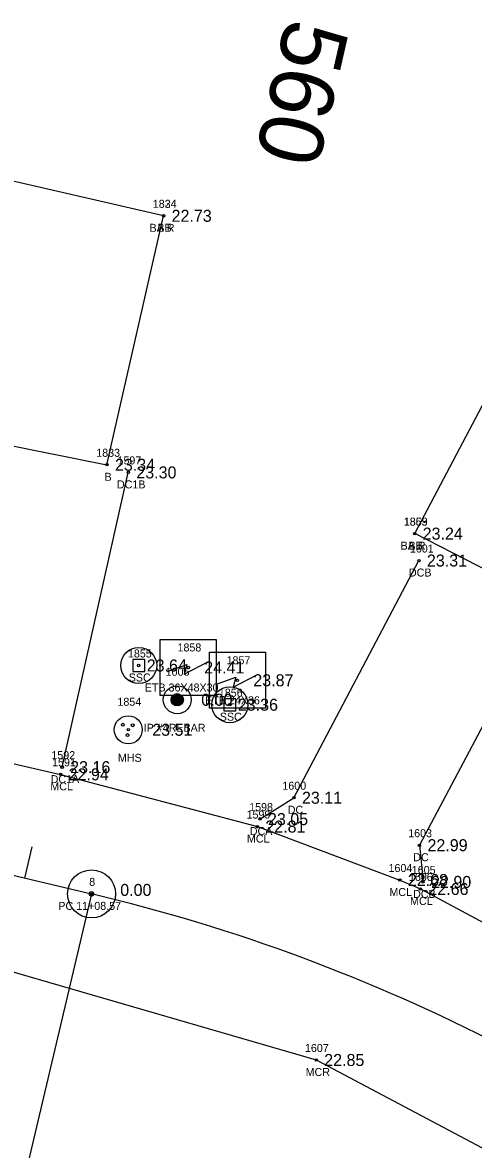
# Model space of a CAD drawing. Extents: x 2654414 to 2656963, y 761776 to 764965.
# Drawn here: x 2655707.7 to 2655764.1, y 762727.3 to 762868.1 of the extents above; entities that cross this region are included whole.
import ezdxf

# ---------------------------------------------------------------- set-up
doc = ezdxf.new("R2010")
doc.units = 0
for name, color, linetype in [('RD_EX_Bldg', 7, 'Continuous'), ('RD_EX_Bldg_txCode', 7, 'Continuous'), ('RD_EX_Conc', 7, 'Continuous'), ('RD_EX_Conc_txCode', 7, 'Continuous'), ('RD_EX_DR_Inlet', 7, 'Continuous'), ('RD_EX_DV_Prop_txCode', 7, 'Continuous'), ('RD_EX_DV_PropPin', 7, 'Continuous'), ('RD_EX_TX_Bldg_ELEV', 7, 'Continuous'), ('RD_EX_TX_Conc_ELEV', 7, 'Continuous'), ('RD_EX_TX_DV_Prop_ELEV', 7, 'Continuous'), ('RD_EX_TX_UT_ELEV', 7, 'Continuous'), ('RD_EX_UT', 7, 'Continuous'), ('RD_EX_UT_txCode', 7, 'Continuous'), ('RD_HC_Cl', 7, 'Continuous'), ('RD_HC_Data', 7, 'Continuous'), ('RD_HC_Data_Tic', 7, 'Continuous'), ('RD_HC_Survey_ELEV', 7, 'Continuous'), ('RD_HC_TX_Sta50', 7, 'Continuous'), ('RD_HC_txCode', 7, 'Continuous'), ('RD_SMD_Locator', 7, 'Continuous')]:
    doc.layers.add(name, color=color, linetype=linetype)

msp = doc.modelspace()

# ---------------------------------------------------------------- linework, layer by layer
at = {"layer": 'RD_EX_Bldg'}
for points in [[(2655725.31, 762843.91), (2655691.97, 762851.59), (2655684.61, 762819.54), (2655718.23, 762812.81), (2655725.31, 762843.91)], [(2655756.7, 762804.21), (2655774.78, 762838.43), (2655800.99, 762824.42), (2655783.66, 762790.4), (2655756.7, 762804.21)]]:
    msp.add_lwpolyline(points, dxfattribs=at)
at = {"layer": 'RD_EX_Conc'}
msp.add_line((2655712.63, 762775.04), (2655720.9, 762811.86), dxfattribs=at)
for points in [[(2655737.36, 762768.55), (2655741.61, 762771.22), (2655757.23, 762800.85)], [(2655647.95, 762795.55), (2655656.5, 762788.85), (2655668.3, 762784.32), (2655695.43, 762778.05), (2655712.44, 762774.14), (2655737.03, 762767.62), (2655754.84, 762760.94), (2655757.41, 762759.82), (2655785.93, 762744.56)], [(2655771.89, 762792.77), (2655757.3, 762765.29), (2655757.75, 762760.7)], [(2655638.83, 762758.42), (2655640.65, 762759.07), (2655648.88, 762760.53), (2655656.27, 762760.57), (2655663.1, 762759.53), (2655700.27, 762751.26), (2655744.39, 762738.46), (2655772.67, 762723.5), (2655774.32, 762722.61)]]:
    msp.add_lwpolyline(points, dxfattribs=at)
at = {"layer": 'RD_EX_DR_Inlet'}
for centre, radius in [((2655720.89, 762779.71), 1.75), ((2655720.22, 762780.34), 0.175), ((2655720.8, 762779.05), 0.175), ((2655721.45, 762780.27), 0.175)]:
    msp.add_circle(centre, radius, dxfattribs=at)
at = {"layer": 'RD_EX_DV_PropPin'}
for p, q in [((2655726.28, 762783.26), (2655726.28, 762783.65)), ((2655726.32, 762783.16), (2655726.32, 762783.75)), ((2655726.35, 762783.09), (2655726.35, 762783.82)), ((2655726.39, 762783.03), (2655726.39, 762783.88)), ((2655726.42, 762782.98), (2655726.42, 762783.93)), ((2655726.46, 762782.94), (2655726.46, 762783.97)), ((2655726.49, 762782.9), (2655726.49, 762784.01)), ((2655726.53, 762782.87), (2655726.53, 762784.04)), ((2655726.56, 762782.85), (2655726.56, 762784.06)), ((2655726.6, 762782.82), (2655726.6, 762784.09)), ((2655726.63, 762782.8), (2655726.63, 762784.11)), ((2655726.67, 762782.78), (2655726.67, 762784.13)), ((2655726.7, 762782.76), (2655726.7, 762784.15)), ((2655726.74, 762782.75), (2655726.74, 762784.16)), ((2655726.77, 762782.73), (2655726.77, 762784.18)), ((2655726.81, 762782.72), (2655726.81, 762784.19)), ((2655726.84, 762782.71), (2655726.84, 762784.2)), ((2655726.88, 762782.71), (2655726.88, 762784.2)), ((2655726.91, 762782.7), (2655726.91, 762784.21)), ((2655726.95, 762782.7), (2655726.95, 762784.21)), ((2655726.98, 762782.69), (2655726.98, 762784.22)), ((2655727.02, 762782.69), (2655727.02, 762784.22)), ((2655727.05, 762782.69), (2655727.05, 762784.22)), ((2655727.09, 762782.7), (2655727.09, 762784.21)), ((2655727.12, 762782.7), (2655727.12, 762784.21)), ((2655727.16, 762782.71), (2655727.16, 762784.2)), ((2655727.19, 762782.71), (2655727.19, 762784.2)), ((2655727.23, 762782.72), (2655727.23, 762784.19)), ((2655727.26, 762782.73), (2655727.26, 762784.18)), ((2655727.3, 762782.75), (2655727.3, 762784.16)), ((2655727.33, 762782.76), (2655727.33, 762784.15)), ((2655727.37, 762782.78), (2655727.37, 762784.13)), ((2655727.4, 762782.8), (2655727.4, 762784.11)), ((2655727.44, 762782.82), (2655727.44, 762784.09)), ((2655727.47, 762782.85), (2655727.47, 762784.06)), ((2655727.51, 762782.87), (2655727.51, 762784.04)), ((2655727.54, 762782.9), (2655727.54, 762784.01)), ((2655727.58, 762782.94), (2655727.58, 762783.97)), ((2655727.61, 762782.98), (2655727.61, 762783.93)), ((2655727.65, 762783.03), (2655727.65, 762783.88)), ((2655727.68, 762783.09), (2655727.68, 762783.82)), ((2655727.72, 762783.16), (2655727.72, 762783.75)), ((2655727.75, 762783.26), (2655727.75, 762783.65))]:
    msp.add_line(p, q, dxfattribs=at)
for radius in [1.75, 0.761]:
    msp.add_circle((2655727.02, 762783.46), radius, dxfattribs=at)
at = {"layer": 'RD_EX_UT'}
for p, q in [((2655722.95, 762788.49), (2655721.45, 762788.49)), ((2655721.45, 762788.49), (2655721.45, 762786.99)), ((2655722.95, 762786.99), (2655722.95, 762788.49)), ((2655721.45, 762786.99), (2655722.95, 762786.99)), ((2655734.34, 762783.59), (2655732.84, 762783.59)), ((2655732.84, 762783.59), (2655732.84, 762782.09)), ((2655734.34, 762782.09), (2655734.34, 762783.59)), ((2655732.84, 762782.09), (2655734.34, 762782.09))]:
    msp.add_line(p, q, dxfattribs=at)
for points in [[(2655724.89, 762783.99), (2655724.89, 762790.99), (2655731.89, 762790.99), (2655731.89, 762783.99)], [(2655731.03, 762782.39), (2655731.03, 762789.39), (2655738.03, 762789.39), (2655738.03, 762782.39)]]:
    msp.add_lwpolyline(points, close=True, dxfattribs=at)
for points in [[(2655725.79, 762786.98), (2655728.21, 762787.88), (2655727.87, 762786.64), (2655730.91, 762788.23)], [(2655731.93, 762785.39), (2655734.35, 762786.29), (2655734, 762785.04), (2655737.05, 762786.63)]]:
    msp.add_lwpolyline(points, dxfattribs=at)
for centre in [(2655722.2, 762787.74), (2655733.59, 762782.84)]:
    msp.add_circle(centre, 2.25, dxfattribs=at)
at = {"layer": 'RD_HC_Cl'}
msp.add_line((2655610.65, 762784.24), (2655716.3, 762759.21), dxfattribs=at)
msp.add_arc((2655664.41, 762540.27), 225, 48.7013, 76.6686, dxfattribs=at)
at = {"layer": 'RD_HC_Data'}
msp.add_line((2655716.3, 762759.21), (2655689.33, 762645.42), dxfattribs=at)
for radius in [3, 0.282]:
    msp.add_circle((2655716.3, 762759.21), radius, dxfattribs=at)
at = {"layer": 'RD_HC_Data_Tic'}
msp.add_line((2655707.95, 762761.18), (2655708.87, 762765.08), dxfattribs=at)
at = {"layer": 'RD_SMD_Locator'}
for centre in [(2655725.31, 762843.91), (2655725.31, 762843.91), (2655718.23, 762812.81), (2655720.9, 762811.86), (2655756.7, 762804.21), (2655756.7, 762804.21), (2655757.23, 762800.85), (2655722.2, 762787.74), (2655728.39, 762787.49), (2655734.53, 762785.89), (2655727.02, 762783.46), (2655733.59, 762782.84), (2655720.89, 762779.71), (2655712.63, 762775.04), (2655712.44, 762774.14), (2655741.61, 762771.22), (2655737.36, 762768.55), (2655737.03, 762767.62), (2655757.3, 762765.29), (2655754.84, 762760.94), (2655757.75, 762760.7), (2655757.41, 762759.82), (2655716.3, 762759.21), (2655744.39, 762738.46)]:
    msp.add_circle(centre, 0.15, dxfattribs=at)

# ---------------------------------------------------------------- texts
at = {"layer": 'RD_EX_Bldg_txCode'}
for s, p in [('1824', (2655723.96, 762844.91)), ('1834', (2655723.96, 762844.91)), ('BA R', (2655723.55, 762841.91)), ('BB', (2655724.53, 762841.91)), ('1833', (2655716.89, 762813.81)), ('B', (2655717.93, 762810.81)), ('1863', (2655755.33, 762805.21)), ('1859', (2655755.35, 762805.21)), ('BA R', (2655754.94, 762802.21)), ('BB', (2655755.92, 762802.21))]:
    msp.add_text(s, height=1, dxfattribs=at).set_placement(p)
at = {"layer": 'RD_EX_Conc_txCode'}
for s, p in [('1597', (2655719.55, 762812.86)), ('DC1B', (2655719.48, 762809.86)), ('1601', (2655756.1, 762801.85)), ('DCB', (2655755.98, 762798.85)), ('1592', (2655711.28, 762776.04)), ('1591', (2655711.37, 762775.14)), ('DC1A', (2655711.19, 762773.04)), ('MCL', (2655711.15, 762772.14)), ('1600', (2655740.16, 762772.22)), ('1599', (2655735.68, 762768.62)), ('1598', (2655736.01, 762769.55)), ('DC', (2655740.83, 762769.22)), ('MCL', (2655735.73, 762765.62)), ('DCA', (2655736.09, 762766.55)), ('1603', (2655755.89, 762766.29)), ('DC', (2655756.52, 762763.29)), ('1604', (2655753.43, 762761.94)), ('1605', (2655756.34, 762761.7)), ('1606', (2655755.98, 762760.82)), ('MCL', (2655753.54, 762758.94)), ('DCB', (2655756.5, 762758.7)), ('MCL', (2655756.12, 762757.82)), ('1607', (2655742.98, 762739.46)), ('MCR', (2655743.07, 762736.46))]:
    msp.add_text(s, height=1, dxfattribs=at).set_placement(p)
at = {"layer": 'RD_EX_DV_Prop_txCode'}
for s, p in [('1006', (2655725.57, 762786.46)), ('IP #4REBAR', (2655722.82, 762779.46))]:
    msp.add_text(s, height=1, dxfattribs=at).set_placement(p)
at = {"layer": 'RD_EX_TX_Bldg_ELEV'}
for s, p in [('22.73', (2655726.31, 762843.16)), ('22.73', (2655726.31, 762843.16)), ('23.34', (2655719.23, 762812.06)), ('23.24', (2655757.7, 762803.46)), ('23.24', (2655757.7, 762803.46))]:
    msp.add_text(s, height=1.5, dxfattribs=at).set_placement(p)
at = {"layer": 'RD_EX_TX_Conc_ELEV'}
for s, p in [('23.30', (2655721.9, 762811.11)), ('23.31', (2655758.23, 762800.1)), ('22.94', (2655713.44, 762773.39)), ('23.16', (2655713.63, 762774.29)), ('23.11', (2655742.61, 762770.47)), ('23.05', (2655738.36, 762767.8)), ('22.81', (2655738.03, 762766.87)), ('22.99', (2655758.3, 762764.54)), ('22.68', (2655755.84, 762760.19)), ('22.90', (2655758.75, 762759.95)), ('22.66', (2655758.41, 762759.07)), ('22.85', (2655745.39, 762737.71))]:
    msp.add_text(s, height=1.5, dxfattribs=at).set_placement(p)
at = {"layer": 'RD_EX_TX_DV_Prop_ELEV'}
msp.add_text('0.00', height=1.5, dxfattribs=at).set_placement((2655730.02, 762782.71))
at = {"layer": 'RD_EX_TX_UT_ELEV'}
for s, p in [('23.64', (2655723.2, 762786.99)), ('24.41', (2655730.39, 762786.74)), ('23.87', (2655736.53, 762785.14)), ('23.36', (2655734.59, 762782.09)), ('23.51', (2655723.89, 762778.96))]:
    msp.add_text(s, height=1.5, dxfattribs=at).set_placement(p)
at = {"layer": 'RD_EX_UT_txCode'}
for s, p in [('1858', (2655727.05, 762789.49)), ('1855', (2655720.85, 762788.74)), ('1857', (2655733.18, 762787.89)), ('SSC', (2655720.95, 762785.74)), ('ETB 36X48X30', (2655722.96, 762784.49)), ('1856', (2655732.22, 762783.84)), ('1854', (2655719.54, 762782.71)), ('ETB 24X36', (2655730.51, 762782.89)), ('SSC', (2655732.34, 762780.84)), ('MHS', (2655719.6, 762775.71))]:
    msp.add_text(s, height=1, dxfattribs=at).set_placement(p)
at = {"layer": 'RD_HC_Survey_ELEV'}
msp.add_text('0.00', height=1.5, dxfattribs=at).set_placement((2655719.89, 762758.95))
at = {"layer": 'RD_HC_TX_Sta50'}
msp.add_text('560', height=8, rotation=257.149, dxfattribs=at).set_placement((2655740.72, 762868.83))
at = {"layer": 'RD_HC_txCode'}
for s, p in [('8', (2655716.01, 762760.21)), ('PC 11+08.57', (2655712.15, 762757.21))]:
    msp.add_text(s, height=1, dxfattribs=at).set_placement(p)

doc.saveas('drawing.dxf')
